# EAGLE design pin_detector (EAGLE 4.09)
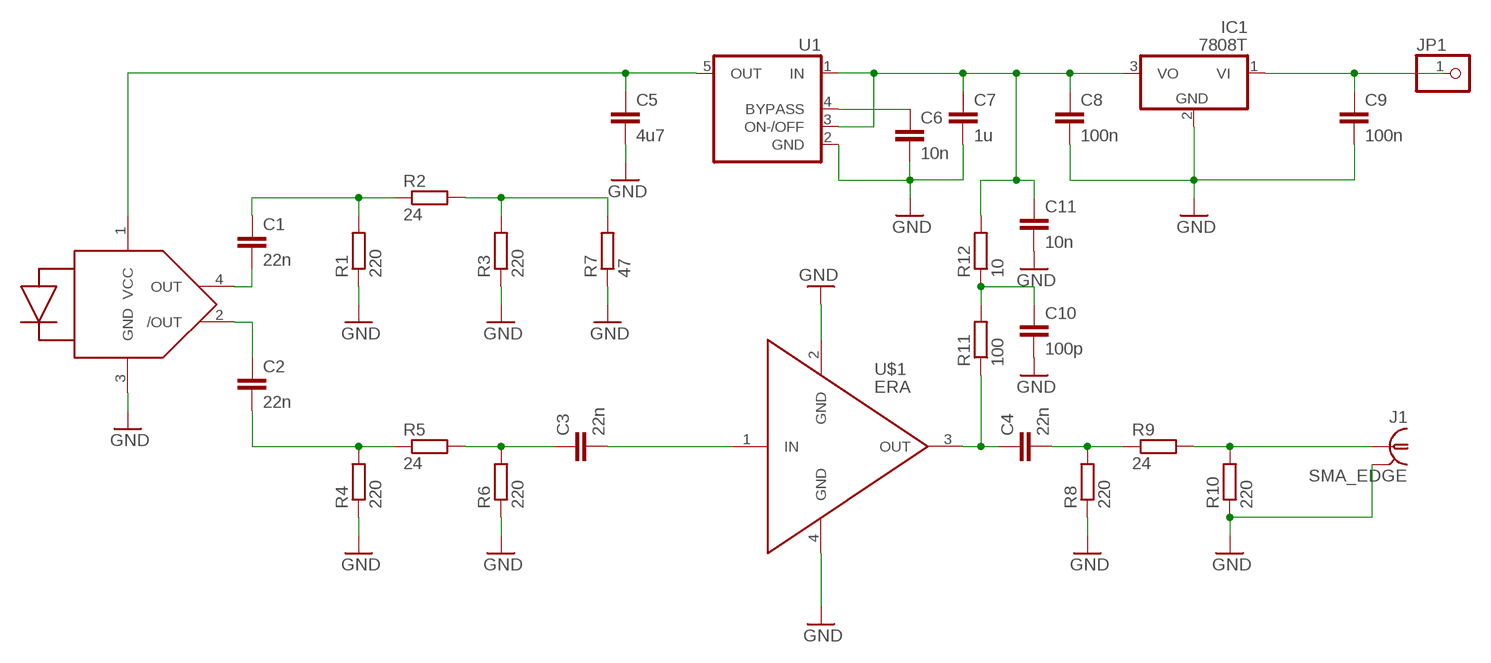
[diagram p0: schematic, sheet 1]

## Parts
C1  22n  C-EUC0805  [C0805]
C2  22n  C-EUC0805  [C0805]
C3  22n  C-EUC0805  [C0805]
C4  22n  C-EUC0805  [C0805]
C5  4u7  C-EUC1206  [C1206]
C6  10n  C-EUC0805  [C0805]
C7  1u  C-EUC1206  [C1206]
C8  100n  C-EUC1206  [C1206]
C9  100n  C-EUC1206  [C1206]
C10  100p  C-EUC0805  [C0805]
C11  10n  C-EUC0805  [C0805]
D1  PIN_D  [PIN_D]
IC1  7808T  [TO220H]
J1  SMA_EDGE  [SMA_EDGE]
JP1  PINHD-1X1  [1X01]
R1  220  R-EU_R0805  [R0805]
R2  24  R-EU_R0805  [R0805]
R3  220  R-EU_R0805  [R0805]
R4  220  R-EU_R0805  [R0805]
R5  24  R-EU_R0805  [R0805]
R6  220  R-EU_R0805  [R0805]
R7  47  R-EU_R0805  [R0805]
R8  220  R-EU_R0805  [R0805]
R9  24  R-EU_R0805  [R0805]
R10  220  R-EU_R0805  [R0805]
R11  100  R-EU_R1206  [R1206]
R12  10  R-EU_R0805  [R0805]
U1  LP2985  [SOT23M5]
U$1  ERA  [ERA]

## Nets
GND: C5.2 C6.2 C7.2 C8.2 C9.2 C10.2 C11.2 D1.3(GND) IC1.2(GND) J1.1(GND) R1.1 R3.1 R4.1 R6.1 R7.1 R8.1 R10.1 U1.2(GND) U$1.2(GND) U$1.4(GND)
N$1: C1.2 D1.4(OUT)
N$2: C1.1 R1.2 R2.1
N$4: R2.2 R3.2 R7.2
N$6: C10.1 R11.2 R12.1
N$7: C2.1 D1.2(/OUT)
N$8: C2.2 R4.2 R5.1
N$9: C3.1 R5.2 R6.2
N$11: C9.1 IC1.1(VI) JP1.1
N$12: C4.2 R8.2 R9.1
N$13: J1.2 R9.2 R10.2
N$16: C3.2 U$1.1(IN)
N$17: C4.1 R11.1 U$1.3(OUT)
N$19: C7.1 C8.1 C11.1 IC1.3(VO) R12.2 U1.1(IN) U1.3(ON-/OFF)
N$21: C6.1 U1.4(BYPASS)
VCC: C5.1 D1.1(VCC) U1.5(OUT)

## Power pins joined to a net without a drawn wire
GND: J1.3(GND) J1.4(GND) J1.5(GND)

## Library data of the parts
C1-C11 = rcl:C-EU: CAPACITOR, European symbol
D1 = lhcb:PIN_D: HFD3381-102 2.5Gbps PIN Diode, 850 nm MM
IC1 = linear:78*: Positive VOLTAGE REGULATOR
J1 = lhcb1:SMA_EDGE
JP1 = pinhead:PINHD-1X1: PIN HEADER
R1-R12 = rcl:R-EU_: RESISTOR, European symbol
U1 = v-reg1:LP2985
U$1 = lhcb:ERA: ERA Broadband Amplifier from Mini-Circuits

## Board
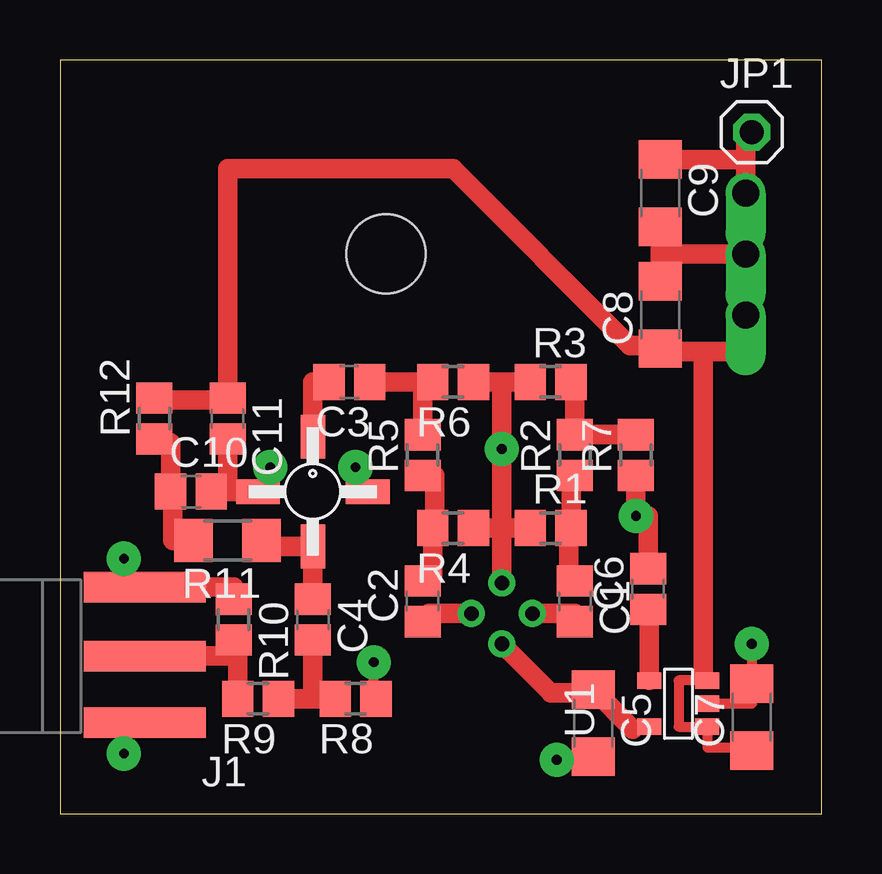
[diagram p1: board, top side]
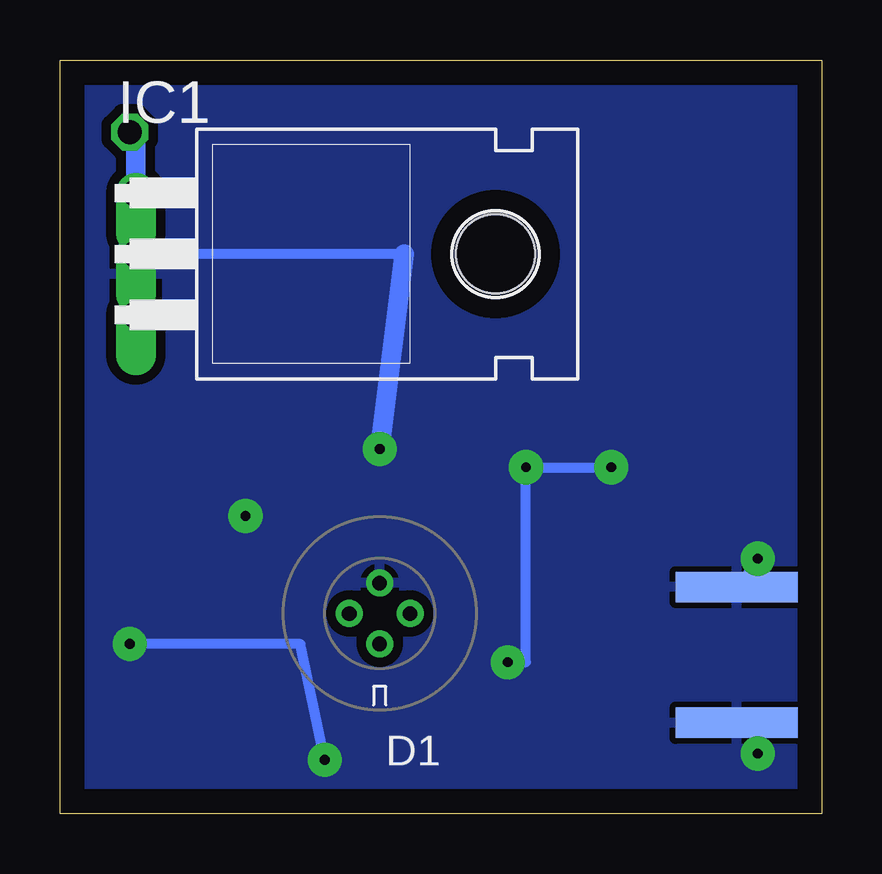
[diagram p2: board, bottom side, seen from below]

Size 31.73 x 31.42 mm. Coordinates in mm from the lower left corner, seen from the top.
Outline: 0,0 31.73,0 31.73,31.42 0,31.42 0,0
Copper layers used: Top, Bottom
bRestrict: area 18.2,7.8 to 18.7,8.9

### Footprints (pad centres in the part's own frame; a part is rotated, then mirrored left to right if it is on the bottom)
C0805 = smd 1.3 x 1.5: 1 -0.85,0; 2 0.85,0
C1206 = smd 1.6 x 1.8: 1 -1.4,0; 2 1.4,0
PIN_D = drill 0.61 round: 1 0,1.27; 2 -1.27,0; 3 0,-1.27; 4 1.27,0
TO220H = drill 1.118 offset: 1 -2.54,-10.16; 2 0,-10.16; 3 2.54,-10.16 | hole 3.302: 0,4.826
SMA_EDGE = smd 1.27 x 5.08: 1 -2.775,-2.65; 2 0,-2.65; 3 2.875,-2.65 | smd 1.27 x 5.08 bottom: 4 -2.775,-2.65; 5 2.875,-2.65
1X01 = drill 1.016 octagon: 1 0,0
R0805 = smd 1.3 x 1.5: 1 -0.85,0; 2 0.85,0
R1206 = smd 1.6 x 1.803: 1 -1.422,0; 2 1.422,0
SOT23M5 = smd 0.686 x 0.991: 1 -0.914,-1.448; 2 0.051,-1.448; 3 1.016,-1.448; 4 1.016,0.965; 5 -0.914,0.965
ERA = smd 1.829 x 1.016: 1 -2.286,0; 3 2.286,0 | smd 1.016 x 1.829: 2 0,-2.286; 4 0,2.286

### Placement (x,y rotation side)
C1  21.46,8.85 270 top
C2  15.11,8.85 90 top
C3  12.06,18 180 top
C4  10.54,8.09 270 top
C5  22.22,3.77 270 top
C6  24.51,9.36 90 top
C7  28.82,4.03 90 top
C8  25.01,20.79 90 top
C9  25.01,25.87 270 top
C10  5.46,13.42 0 top
C11  6.98,16.47 270 top
D1  18.41,8.34 180 bottom
IC1  18.41,23.33 270 bottom
J1  0.88,6.57 90 top
JP1  28.82,28.41 0 top
R1  20.44,11.9 0 top
R2  21.46,14.95 90 top
R3  20.44,18 0 top
R4  16.38,11.9 180 top
R5  15.11,14.95 90 top
R6  16.38,18 180 top
R7  24,14.95 90 top
R8  12.31,4.79 180 top
R9  8.25,4.79 180 top
R10  7.23,8.09 270 top
R11  6.98,11.39 180 top
R12  3.93,16.47 90 top
U1  25.52,4.53 90 top
U$1  10.54,13.42 270 top

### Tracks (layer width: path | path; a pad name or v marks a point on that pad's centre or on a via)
GND  (via drill 0.41 pad 1.42)
  Top 0.406: 26.92,4.53 U1.2 28.82,4.58 28.82,5.3 | 28.82,5.3 C7.2 | v24,12.41 R7.1 | R1.1 19.43,11.9 | 18.41,18 R3.1 | 6.47,13.42 U$1.2 8.76,13.42 | 6.47,13.42 C10.2 | 6.47,13.42 6.98,13.42 | 12.31,13.42 U$1.4 | R8.1 13.08,4.79 v13.08,6.31 | C5.2 22.22,2.25 v20.7,2.25 | v28.82,7.07 28.82,5.3 | 25.01,23.33 25.01,24.35 C9.2 | 7.23,9.44 R10.1 | J1.1 3.42,3.77 2.52,3.77 2.52,2.5 v2.66,2.5 | J1.5 2.58,9.44 2.66,9.36 v2.66,10.63
  Top 0.813: C6.2 24.51,12.41 v24,12.41 R7.1 | D1.3 18.41,11.9 | 18.41,11.9 R4.1 | R3.1 R6.1 | 18.41,18 v18.41,15.2 18.41,11.9 | 18.41,11.9 R1.1 | 6.98,13.42 C11.2 | U$1.2 C10.2 | v8.76,14.44 8.76,13.42 | v12.31,14.44 12.31,13.42 | IC1.2 25.01,23.33 | 25.01,24.35 C8.2 | J1.5 7.23,9.44
  Bottom 0.406: 17.39,23.33 IC1.2 | v8.76,14.44 v12.31,14.44 12.31,6.31 v13.08,6.31 | v20.7,2.25 21.71,7.07 v28.82,7.07 | v24,12.41 24.51,12.41 | v2.66,2.5 2.41,2.5 | J1.5 2.52,10.63 v2.66,10.63
  Bottom 0.813: v18.41,15.2 17.39,23.33
  pour Bottom (isolate 0.406): 0.63,30.95 0.63,0.47 31.11,0.47 31.11,30.95
N$1
  Top 0.406: C1.2 21.46,8.34
  Top 0.813: 21.46,8.34 D1.4
N$2
  Top 0.406: 21.2,11.9 R1.2 | C1.1 21.2,9.7 | R2.1 21.46,13.93 21.29,13.93
  Top 0.813: 21.2,9.7 21.2,11.9 | R1.2 21.29,13.93
N$4
  Top 0.406: R7.2 24,15.71 | R3.2 21.46,18
  Top 0.813: R7.2 R2.2 21.46,18
N$6
  Top 0.406: R11.2 4.69,11.39 | 4.69,13.17 4.61,13.17 C10.1 | R12.1 3.93,15.46 4.61,15.46
  Top 0.813: 4.69,11.39 4.69,13.17 | C10.1 4.61,15.46
N$7
  Top 0.406: C2.1 15.36,8 15.36,8.34
  Top 0.813: 15.36,8.34 D1.2
N$8
  Top 0.406: C2.2 15.11,9.87 15.53,9.87 | R4.2 15.62,11.9 | 15.62,14.1 R5.1
  Top 0.813: 15.53,9.87 R4.2 | 15.62,11.9 15.62,14.1
N$9
  Top 0.406: 15.62,18 R6.2 15.11,18 | C3.1 12.82,18
  Top 0.813: 15.11,18 R5.2 | C3.1 R6.2
N$11
  Top 0.406: 28.57,27.27 IC1.1 | 28.57,28.41 JP1.1
  Top 0.813: C9.1 28.57,27.27 | IC1.1 28.57,28.41
  Bottom 0.406: 28.57,28.41 JP1.1
  Bottom 0.813: IC1.1 28.57,28.41
N$12
  Top 0.406: 11.55,4.79 R8.2 10.54,4.79
  Top 0.813: 10.54,4.79 C4.2 | R9.1 R8.2
N$13
  Top 0.406: 7.23,7.07 7.23,6.82 7.4,6.82 | 7.23,7.07 R10.2 | 7.23,6.57 7.23,7.07
  Top 0.813: 7.4,6.82 R9.2 | J1.2 7.23,6.57
N$16
  Top 0.406: 10.54,18 C3.2
  Top 0.813: U$1.1 10.54,18
N$17
  Top 0.406: C4.1 10.54,8.85 | 8.4,11.14 R11.1
  Top 0.813: C4.1 U$1.3 8.4,11.14
N$19
  Top 0.406: C7.1 28.82,2.76 26.97,2.76 U1.1 25.78,3.62 25.78,5.55 U1.3 27.05,5.55 27.05,5.8 26.79,5.8 | 6.98,17.23 C11.1 | R12.2 3.93,17.23 | 25.01,19.52 C8.1 25.01,19.27
  Top 0.813: 3.93,17.23 6.98,17.23 | IC1.3 28.57,19.27 26.79,19.27 | 25.01,19.27 26.79,19.27 | 26.79,19.27 26.79,5.8 | C11.1 6.98,26.89 16.38,26.89 23.74,19.52 25.01,19.52
N$21
  Top 0.406: 24.56,8.34 C6.1
  Top 0.813: U1.4 24.56,8.34
VCC
  Top 0.406: 22.22,5.04 C5.1 | U1.5 24.51,3.57 24.51,3.52 23.87,3.52
  Top 0.813: D1.1 20.44,5.04 22.22,5.04 | C5.1 23.87,3.52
